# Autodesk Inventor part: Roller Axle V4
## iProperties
Created: 2007-11
Part Number: Roller Axle V4
Document SubType Name: Modeling
Designer: lwoods
Density: 7.84 g/cm^3
Material: Steel, High Strength Low Alloy
Mass: 10.4976 g
Surface Area: 11.0198 cm^2
Volume: 1.33898 cm^3
Author: lwoods
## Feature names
1. Extrusion1
2. Extrusion2
3. Extrusion3
